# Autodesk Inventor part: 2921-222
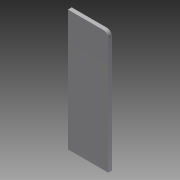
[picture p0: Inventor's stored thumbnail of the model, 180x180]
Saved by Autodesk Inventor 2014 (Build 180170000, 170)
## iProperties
Company: NHTSA/VRTC
Created: 2012-08
Part Number: 2921-222
Material: Steel, Mild
Document SubType Name: Modeling
Designer: Mike Vanvoorhis
Density: 7.86 g/cm^3
Mass: 2315.85 g
Surface Area: 695.561 cm^2
Volume: 294.637 cm^3
Project: CHILD SIDE IMPACT SLED
Description: IMPACTOR STOP SIDE GUSSET PLATE
Stock Number: PL 9.5 (3/8") x 101.6 (4") x 304.8 (12")
Appearance: Steel
Author: Dave Walker
Title: Impactor Stop Side Gusset Plate
Subject: Child Side Impact Sled
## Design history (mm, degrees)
sketch "Sketch1"
  geometry: L1 (0, 0)-(101.6, 0); L2 (101.6, 0)-(101.6, 292.1); L3 (88.9, 304.8)-(0, 304.8); L4 (0, 304.8)-(0, 0); A1 r 12.7 centre (88.9, 292.1) between (101.6, 292.1) and (88.9, 304.8); 1 further point
  constraints: 8 end point, 2 parallel, 2 point on circle, 2 point on line, 2 tangent, 1 centre point, 1 horizontal, 1 perpendicular
  dimensions: "d0" = 101.6 distance of L3.end point (101.6, 304.8); "d1" = 304.8 distance of point (101.6, 304.8) L1.end; "d2" = 12.7 radius of A1
extrude "Extrusion1" new body sketch "Sketch1" distance "d3" = 9.525; taper "d4" = 0 deg
body "Solid1"
